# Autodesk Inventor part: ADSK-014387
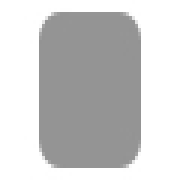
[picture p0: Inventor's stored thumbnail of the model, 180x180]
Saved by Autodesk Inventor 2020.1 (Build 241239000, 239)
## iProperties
Created: 2019-01
Part Number: ADSK-014387
Material: Stahl, weich
Document SubType Name: Modeling
Designer: lutzd
Language: de-DE
Size Designation: 5 x 40 x 40
Categories: <MemberInstance><Categories><Category DisplayName="Sonstige Bauteile" InternalName="5aa15e00-363f-49f2-933f-16f664388e3f" Mnemonic="OTHER"><Category DisplayName
Mass: 61.9577 g
Surface Area: 39.1416 cm^2
Volume: 7.8927 cm^3
Density: 7.85 g/cm^3
Appearance: Semi-Polished(8)
DocNumber: ADSK-014387
Folder: 01 - Themengebiete\Simplification\01 - Packaging machine\Parts\
VDS_Category: 3D Komponenten
VDS_NumSchm: Autodesk
Mass: 0,062 kg
VLT_Material: Stahl, weich
IsCustomPart: 1
Title: end cap
Author: lutzd
Revision Number: -
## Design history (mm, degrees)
sketch "Sketch1"
  geometry: L1 (0, 20.175)-(0, -21.446); L2 (-20.203, 0)-(20.169, 0); L3 (-20, 20)-(20, 20); L4 (20, 20)-(20, -20); L5 (20, -20)-(-20, -20); L6 (-20, -20)-(-20, 20); 1 further point
  constraints: 12 end point, 2 horizontal, 2 parallel, 2 point on line, 1 perpendicular, 1 vertical
  dimensions: "d0" = 40 distance between parallel lines of L5 L3 (= height); "d1" = 20 distance between parallel lines of L2 L3 (= 0.5 x height); "d2" = 40 distance between parallel lines of L6 L4 (= width); "d3" = 20 distance between parallel lines of L6 L1 (= 0.5 x width)
extrude "Extrusion1" new body sketch "Sketch1" distance "d4" = 5 (= thickness); taper "d5" = 0 deg
fillet "Fillet1" dims "d6" = 5 (= fillet), "d7" = 0, "fillet" = 5 [user parameter; used in 1 equation term]
chamfer "Chamfer1" distance "d8" = 0 (computed from chamfer); stored, may be unused: second distance "d9" = 2, angle "d10" = 45 deg; dims "d11" = 0, "chamfer" = 0 [user parameter; used in 1 equation term]
body "Solid1"
other parameters: "thickness" = 5 [user parameter; used in 1 equation term], "width" = 40 [user parameter; used in 2 equation terms], "height" = 40 [user parameter; used in 2 equation terms]
